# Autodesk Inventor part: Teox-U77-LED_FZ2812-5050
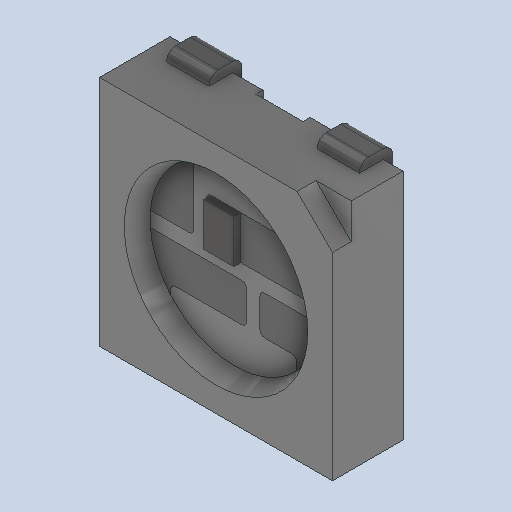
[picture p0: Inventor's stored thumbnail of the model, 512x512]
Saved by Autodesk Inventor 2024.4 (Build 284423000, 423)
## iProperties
Created: 2025-05
Part Number: Teox-U77-LED_FZ2812-5050
Material: Generic
Document SubType Name: Modeling
Designer: AdminForWorker
Density: 1 g/cm^3
Appearance: Default
Title: Teox-U77-LED_FZ2812-5050
Author: AdminForWorker
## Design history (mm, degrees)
feature "Body1"
body "Solid1"
